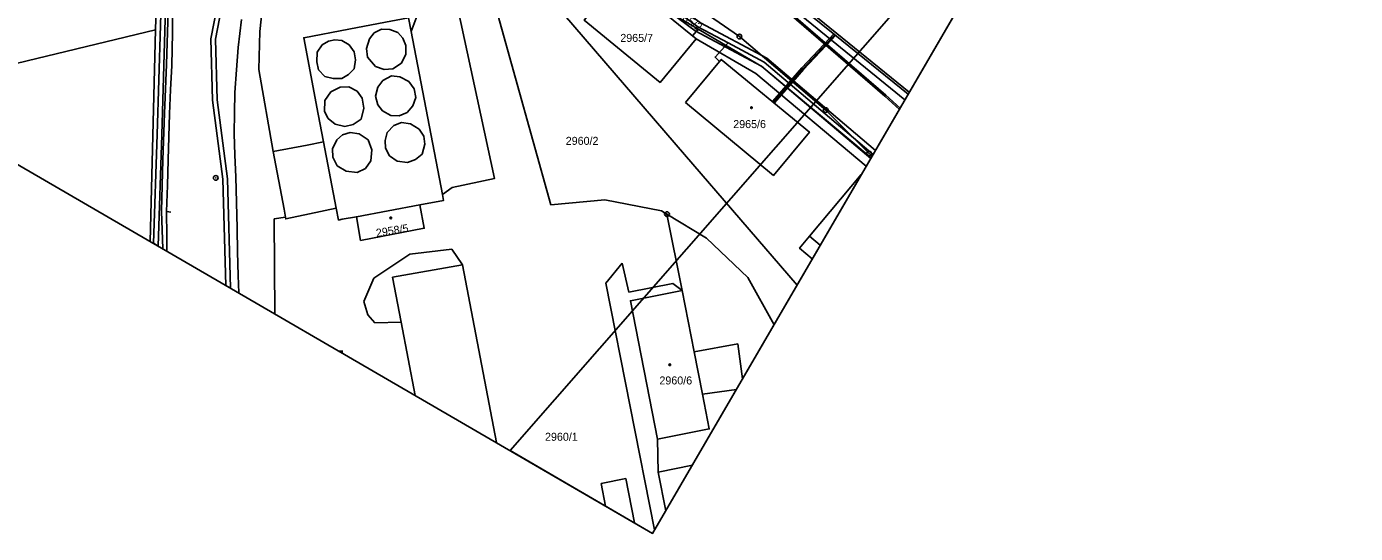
# Model space of a CAD drawing. Extents: x -621168 to -620292, y -1122748 to -1122069.
# Drawn here: x -620574.7 to -620292.4, y -1122748.2 to -1122640.4 of the extents above; entities that cross this region are included whole.
import ezdxf

# ---------------------------------------------------------------- set-up
doc = ezdxf.new("R2010")
doc.units = 0
for name, color, linetype in [('CETIN', 7, 'Continuous'), ('GasNet', 7, 'Continuous'), ('Hranice parcel', 7, 'Continuous'), ('Parcelní čísla', 7, 'Continuous'), ('Rámečky', 7, 'Continuous'), ('Rámečky-tisk', 7, 'Continuous'), ('SSZT-DK', 7, 'Continuous'), ('VAS stoka', 7, 'Continuous'), ('VAS vodovod', 7, 'Continuous'), ('Vnitřní kresba', 7, 'Continuous'), ('Věcná břemena k části', 7, 'Continuous'), ('Značky bodu BP', 7, 'Continuous'), ('Značky budov', 7, 'Continuous'), ('ČD-T', 7, 'Continuous')]:
    doc.layers.add(name, color=color, linetype=linetype)

msp = doc.modelspace()

# ---------------------------------------------------------------- linework, layer by layer
at = {"layer": 'CETIN'}
for points in [[(-620466.49, -1122590.92), (-620402.98, -1122642.16)], [(-620402.98, -1122642.16), (-620404.74, -1122644.03), (-620409.77, -1122649.38), (-620413.72, -1122653.89), (-620414.65, -1122654.95), (-620416.03, -1122656.53)], [(-620404.74, -1122644.03), (-620409.77, -1122649.38)], [(-620402.98, -1122642.16), (-620387.36, -1122654.76)]]:
    msp.add_lwpolyline(points, dxfattribs=at)
at = {"layer": 'GasNet'}
for points in [[(-620545.62, -1122586.36), (-620544.33, -1122585.86), (-620529.1, -1122581.91), (-620527.88, -1122581.68), (-620501.79, -1122593.01), (-620500.52, -1122592.53), (-620484.13, -1122585.56), (-620478.57, -1122583.14), (-620474.2, -1122586.82), (-620449.91, -1122606.86), (-620450.02, -1122607.5), (-620458.5, -1122620.02), (-620458.8, -1122620.62), (-620432.06, -1122640.49), (-620425.64, -1122643.91), (-620417.98, -1122647.99), (-620394.83, -1122667.62)], [(-620543.45, -1122595.16), (-620543.47, -1122603.15), (-620543.79, -1122613), (-620544.07, -1122623.3), (-620544.52, -1122634.84), (-620544.92, -1122648.49), (-620545.38, -1122658.87), (-620545.7, -1122668.76), (-620545.98, -1122679.66), (-620545.73, -1122687.65)], [(-620425.64, -1122643.91), (-620428.38, -1122646.91), (-620427.46, -1122647.86)]]:
    msp.add_lwpolyline(points, dxfattribs=at)
at = {"layer": 'Hranice parcel'}
for p, q in [((-620546.5, -1122612), (-620547.23, -1122641.1)), ((-620547.23, -1122641.1), (-620602.67, -1122654.54)), ((-620547.23, -1122641.1), (-620548.37, -1122686.11)), ((-620435.41, -1122696.52), (-620438.61, -1122680.28)), ((-620440.5, -1122735.14), (-620440.62, -1122728.09))]:
    msp.add_line(p, q, dxfattribs=at)
for points in [[(-620485.21, -1122574.33), (-620466.94, -1122589.51), (-620387.14, -1122654.39)], [(-620502.69, -1122605.61), (-620503.19, -1122607.95), (-620524.52, -1122636.25), (-620525.13, -1122641.47), (-620525.33, -1122649.53), (-620522.29, -1122666.99)], [(-620388.08, -1122656.01), (-620420.38, -1122629.64), (-620446.79, -1122609.88)], [(-620438.61, -1122680.28), (-620439.78, -1122679.56), (-620451.85, -1122677.25), (-620463.28, -1122678.3), (-620478.32, -1122624.38)], [(-620410.99, -1122695.4), (-620434.88, -1122667.63), (-620473.14, -1122623.15)], [(-620452.73, -1122622.13), (-620423.22, -1122642.55), (-620404.9, -1122658.18), (-620395.68, -1122667.41), (-620395.02, -1122667.94)], [(-620486.3, -1122676.15), (-620484.21, -1122674.6), (-620475.28, -1122672.75), (-620485.31, -1122626.04)], [(-620450.04, -1122631.61), (-620448.58, -1122629.86), (-620432.38, -1122643.03)], [(-620432.38, -1122643.03), (-620440.08, -1122652.3), (-620456.23, -1122639.05), (-620450.04, -1122631.61)], [(-620522.29, -1122666.99), (-620515.05, -1122665.61), (-620511.55, -1122664.94), (-620512.68, -1122659.03), (-620515.78, -1122642.8), (-620506.17, -1122640.97), (-620499.9, -1122639.77), (-620493.5, -1122638.55), (-620492.94, -1122641.47), (-620486.3, -1122676.15)], [(-620396.27, -1122670.08), (-620419.73, -1122650.41), (-620432.38, -1122643.03)], [(-620434.7, -1122656.53), (-620427.07, -1122647.39), (-620408.37, -1122662.86), (-620416.01, -1122672.06), (-620434.7, -1122656.53)], [(-620522.29, -1122666.99), (-620519.96, -1122679.22), (-620519.64, -1122680.92)], [(-620407.74, -1122689.82), (-620410.45, -1122687.55), (-620408.32, -1122685), (-620397.34, -1122671.88), (-620397.32, -1122671.9)], [(-620519.64, -1122680.92), (-620519.58, -1122681.29), (-620514.56, -1122680.24), (-620508.86, -1122679.05), (-620508.38, -1122681.54), (-620507.59, -1122681.39), (-620504.59, -1122680.83), (-620503.71, -1122685.86), (-620490.19, -1122683.29), (-620491.13, -1122678.32), (-620486.07, -1122677.38), (-620486.3, -1122676.15)], [(-620438.61, -1122680.28), (-620430.21, -1122685.42), (-620421.46, -1122693.76), (-620415.87, -1122703.8)], [(-620519.64, -1122680.92), (-620522.03, -1122681.32), (-620521.9, -1122701.5)], [(-620492.12, -1122718.82), (-620495.08, -1122703.28), (-620496.9, -1122693.7), (-620482.03, -1122691.1)], [(-620482.03, -1122691.1), (-620474.85, -1122728.86)], [(-620440.62, -1122728.09), (-620446.38, -1122698.69), (-620435.41, -1122696.52)], [(-620440.62, -1122728.09), (-620429.62, -1122725.94), (-620431.07, -1122718.59), (-620432.85, -1122709.54), (-620435.41, -1122696.52)], [(-620508.34, -1122709.39), (-620507.61, -1122709.36), (-620507.58, -1122709.83)], [(-620433.21, -1122733.63), (-620440.5, -1122735.14)], [(-620438.86, -1122743.34), (-620440.5, -1122735.14)]]:
    msp.add_lwpolyline(points, dxfattribs=at)
at = {"layer": 'Rámečky'}
msp.add_line((-620351.12, -1122592.44), (-620471.94, -1122730.56), dxfattribs=at)
msp.add_lwpolyline([(-620471.94, -1122730.56), (-620441.66, -1122748.16), (-620351.12, -1122592.44)], dxfattribs=at)
at = {"layer": 'Rámečky-tisk'}
msp.add_line((-620351.12, -1122592.44), (-620471.94, -1122730.56), dxfattribs=at)
for points in [[(-621018.54, -1122069.17), (-621167.83, -1122325.92), (-620441.66, -1122748.16)], [(-620441.66, -1122748.16), (-620292.37, -1122491.41), (-621018.54, -1122069.17)], [(-620471.94, -1122730.56), (-620441.66, -1122748.16), (-620351.12, -1122592.44)]]:
    msp.add_lwpolyline(points, dxfattribs=at)
at = {"layer": 'SSZT-DK'}
msp.add_lwpolyline([(-621084.33, -1122182.33), (-621080.25, -1122184.04), (-621051.5, -1122198.93), (-620999.37, -1122227), (-620959.93, -1122250.54), (-620931.35, -1122267.52), (-620900.27, -1122286.47), (-620889.15, -1122293.45), (-620783.74, -1122358.82), (-620712.75, -1122398.18), (-620653.12, -1122435.23), (-620617.36, -1122456.74), (-620574.42, -1122482.6), (-620528.16, -1122511.11), (-620496.31, -1122530.83), (-620515.02, -1122558.81), (-620500.38, -1122568.61), (-620465.39, -1122591.45), (-620452.16, -1122605.02), (-620438.23, -1122615.5), (-620392.31, -1122655.21), (-620389.25, -1122658.02)], dxfattribs=at)
at = {"layer": 'VAS stoka'}
msp.add_lwpolyline([(-620529.59, -1122697.03), (-620529.71, -1122693.36), (-620529.82, -1122688.3), (-620529.93, -1122683.25), (-620530.07, -1122677.82), (-620530.21, -1122672.39), (-620530.38, -1122667.76), (-620530.55, -1122663.12), (-620530.49, -1122658.76), (-620530.43, -1122654.4), (-620530.06, -1122649.64), (-620529.7, -1122644.88), (-620528.99, -1122638.95)], dxfattribs=at)
at = {"layer": 'VAS vodovod'}
msp.add_line((-620433.19, -1122642.42), (-620431.98, -1122640.97), dxfattribs=at)
for points in [[(-620395.25, -1122668.33), (-620418.43, -1122648.88), (-620439.22, -1122636.74), (-620439.29, -1122636.69), (-620439.37, -1122636.64), (-620460.45, -1122621.06), (-620460.7, -1122620.9), (-620459.95, -1122619.77), (-620451.51, -1122607.79), (-620450.89, -1122606.96), (-620476.53, -1122586.08), (-620476.53, -1122586.08), (-620476.87, -1122585.61)], [(-620543.55, -1122634.84), (-620543.68, -1122641.77), (-620543.81, -1122648.71), (-620544.05, -1122653.84), (-620544.28, -1122658.97), (-620544.43, -1122663.85), (-620544.59, -1122668.72), (-620544.75, -1122674.23), (-620544.92, -1122679.73), (-620544.87, -1122684.99), (-620544.84, -1122688.17)], [(-620544.92, -1122679.73), (-620544.45, -1122679.79), (-620543.99, -1122679.84)]]:
    msp.add_lwpolyline(points, dxfattribs=at)
at = {"layer": 'Vnitřní kresba'}
for p, q in [((-620487.46, -1122626.56), (-620492.94, -1122641.47)), ((-620500.81, -1122641.76), (-620499.26, -1122640.98)), ((-620499.26, -1122640.98), (-620497.47, -1122641.06)), ((-620497.47, -1122641.06), (-620495.76, -1122641.68)), ((-620511.84, -1122644.32), (-620510.52, -1122643.55)), ((-620510.52, -1122643.55), (-620509.2, -1122643.23)), ((-620509.2, -1122643.23), (-620507.65, -1122643.39)), ((-620507.65, -1122643.39), (-620506.09, -1122644.32)), ((-620502.44, -1122645.1), (-620501.82, -1122643)), ((-620501.82, -1122643), (-620500.81, -1122641.76)), ((-620495.76, -1122641.68), (-620494.75, -1122642.92)), ((-620494.75, -1122642.92), (-620494.06, -1122644.48)), ((-620513, -1122647.9), (-620512.93, -1122645.88)), ((-620512.93, -1122645.88), (-620511.84, -1122644.32)), ((-620506.09, -1122644.32), (-620505.08, -1122645.8)), ((-620505.08, -1122645.8), (-620504.77, -1122647.51)), ((-620502.21, -1122646.96), (-620502.44, -1122645.1)), ((-620500.5, -1122648.9), (-620502.21, -1122646.96)), ((-620494.06, -1122646.26), (-620494.99, -1122648.21)), ((-620494.06, -1122644.48), (-620494.06, -1122646.26)), ((-620512.62, -1122649.6), (-620513, -1122647.9)), ((-620511.3, -1122651), (-620512.62, -1122649.6)), ((-620505.08, -1122649.37), (-620506.25, -1122650.61)), ((-620504.77, -1122647.51), (-620505.08, -1122649.37)), ((-620498.71, -1122649.52), (-620500.5, -1122648.9)), ((-620496.85, -1122649.37), (-620498.71, -1122649.52)), ((-620494.99, -1122648.21), (-620496.85, -1122649.37)), ((-620509.51, -1122651.47), (-620511.3, -1122651)), ((-620507.65, -1122651.47), (-620509.51, -1122651.47)), ((-620506.25, -1122650.61), (-620507.65, -1122651.47)), ((-620500.03, -1122653.33), (-620498.95, -1122651.85)), ((-620498.95, -1122651.85), (-620497.16, -1122650.92)), ((-620497.16, -1122650.92), (-620495.38, -1122651.08)), ((-620495.38, -1122651.08), (-620493.43, -1122652.09)), ((-620493.43, -1122652.09), (-620492.35, -1122653.64)), ((-620511.3, -1122656.13), (-620510.05, -1122654.26)), ((-620510.05, -1122654.26), (-620508.03, -1122653.33)), ((-620508.03, -1122653.33), (-620506.17, -1122653.25)), ((-620506.17, -1122653.25), (-620504.46, -1122654.18)), ((-620504.46, -1122654.18), (-620503.37, -1122655.66)), ((-620500.5, -1122655.19), (-620500.03, -1122653.33)), ((-620500.03, -1122657.06), (-620500.5, -1122655.19)), ((-620492.35, -1122653.64), (-620491.96, -1122655.5)), ((-620511.37, -1122658.46), (-620511.3, -1122656.13)), ((-620502.99, -1122657.76), (-620503.61, -1122660.09)), ((-620503.37, -1122655.66), (-620502.99, -1122657.76)), ((-620499.03, -1122658.3), (-620500.03, -1122657.06)), ((-620492.58, -1122657.29), (-620493.82, -1122658.69)), ((-620491.96, -1122655.5), (-620492.58, -1122657.29)), ((-620510.6, -1122659.93), (-620511.37, -1122658.46)), ((-620509.12, -1122661.17), (-620510.6, -1122659.93)), ((-620503.61, -1122660.09), (-620505.24, -1122661.25)), ((-620497.24, -1122659.31), (-620499.03, -1122658.3)), ((-620495.53, -1122659.39), (-620497.24, -1122659.31)), ((-620496.62, -1122661.48), (-620494.99, -1122660.79)), ((-620493.82, -1122658.69), (-620495.53, -1122659.39)), ((-620494.99, -1122660.79), (-620493.12, -1122661.1)), ((-620507.02, -1122661.64), (-620509.12, -1122661.17)), ((-620508.73, -1122664.51), (-620507.57, -1122663.43)), ((-620507.57, -1122663.43), (-620505.94, -1122662.96)), ((-620505.24, -1122661.25), (-620507.02, -1122661.64)), ((-620505.94, -1122662.96), (-620504, -1122663.19)), ((-620504, -1122663.19), (-620502.06, -1122664.51)), ((-620498.48, -1122664.67), (-620498.02, -1122662.96)), ((-620498.02, -1122662.96), (-620496.62, -1122661.48)), ((-620493.12, -1122661.1), (-620491.26, -1122662.26)), ((-620491.26, -1122662.26), (-620490.25, -1122663.74)), ((-620490.25, -1122663.74), (-620490.02, -1122665.44)), ((-620508.86, -1122679.05), (-620511.55, -1122664.94)), ((-620509.67, -1122666.38), (-620508.73, -1122664.51)), ((-620509.59, -1122668.16), (-620509.67, -1122666.38)), ((-620502.06, -1122664.51), (-620501.28, -1122666.61)), ((-620501.28, -1122666.61), (-620501.51, -1122668.94)), ((-620498.41, -1122666.3), (-620498.48, -1122664.67)), ((-620497.55, -1122667.93), (-620498.41, -1122666.3)), ((-620490.02, -1122665.44), (-620490.64, -1122667.54)), ((-620508.66, -1122670.03), (-620509.59, -1122668.16)), ((-620501.51, -1122668.94), (-620502.68, -1122670.57)), ((-620495.92, -1122669.02), (-620497.55, -1122667.93)), ((-620493.75, -1122669.33), (-620495.92, -1122669.02)), ((-620492.04, -1122668.71), (-620493.75, -1122669.33)), ((-620490.64, -1122667.54), (-620492.04, -1122668.71)), ((-620506.79, -1122671.19), (-620508.66, -1122670.03)), ((-620504.46, -1122671.42), (-620506.79, -1122671.19)), ((-620502.68, -1122670.57), (-620504.46, -1122671.42)), ((-620504.59, -1122680.83), (-620491.13, -1122678.32)), ((-620406.05, -1122686.9), (-620408.32, -1122685)), ((-620500.9, -1122693.92), (-620493.22, -1122688.81)), ((-620493.22, -1122688.81), (-620484.3, -1122687.75)), ((-620484.3, -1122687.75), (-620482.03, -1122691.1)), ((-620448.12, -1122690.72), (-620451.61, -1122694.97)), ((-620446.75, -1122696.88), (-620448.12, -1122690.72)), ((-620503.01, -1122698.89), (-620500.9, -1122693.92)), ((-620451.61, -1122694.97), (-620441.23, -1122747.41)), ((-620437.36, -1122695.04), (-620446.75, -1122696.88)), ((-620437.36, -1122695.04), (-620435.41, -1122696.52)), ((-620502.18, -1122701.71), (-620503.01, -1122698.89)), ((-620500.67, -1122703.36), (-620502.18, -1122701.71)), ((-620495.08, -1122703.28), (-620500.67, -1122703.36)), ((-620432.85, -1122709.54), (-620423.56, -1122707.88)), ((-620423.56, -1122707.88), (-620422.57, -1122715.32)), ((-620423.88, -1122717.57), (-620431.07, -1122718.59)), ((-620447.35, -1122736.5), (-620452.59, -1122737.55)), ((-620445.54, -1122745.91), (-620447.35, -1122736.5)), ((-620451.65, -1122742.35), (-620452.59, -1122737.55))]:
    msp.add_line(p, q, dxfattribs=at)
at = {"layer": 'Věcná břemena k části'}
for p, q in [((-620395.34, -1122668.49), (-620394.32, -1122666.74)), ((-620547.72, -1122686.49), (-620546.73, -1122687.07)), ((-620532.32, -1122695.44), (-620531.3, -1122696.04))]:
    msp.add_line(p, q, dxfattribs=at)
for points in [[(-620394.32, -1122666.74), (-620417.42, -1122647.16), (-620431.52, -1122639.64), (-620457.44, -1122620.38), (-620448.45, -1122606.75), (-620478.4, -1122581.98), (-620488.36, -1122586.21), (-620487.32, -1122587.95), (-620478.74, -1122584.3), (-620451.11, -1122607.15), (-620460.16, -1122620.86), (-620432.6, -1122641.34), (-620418.54, -1122648.82), (-620395.34, -1122668.49)], [(-620545.88, -1122628.46), (-620546.91, -1122663.38), (-620547.72, -1122686.49)], [(-620546.73, -1122687.07), (-620545.91, -1122663.42), (-620544.9, -1122629)], [(-620534.2, -1122636.18), (-620535.53, -1122643.03), (-620535.16, -1122656.08), (-620532.94, -1122672.87), (-620532.32, -1122695.44)], [(-620531.3, -1122696.04), (-620531.94, -1122672.79), (-620534.16, -1122656), (-620534.53, -1122643.11), (-620533.24, -1122636.48)]]:
    msp.add_lwpolyline(points, dxfattribs=at)
for points in [[(-620414.7, -1122654.63), (-620414.31, -1122654.95), (-620411.9, -1122652.2), (-620409.58, -1122649.55), (-620403.69, -1122643.27), (-620402.81, -1122642.33), (-620403.17, -1122641.99), (-620404.07, -1122642.95), (-620409.97, -1122649.21), (-620412.29, -1122651.87)], [(-620415.83, -1122656.69), (-620414.31, -1122654.95), (-620414.7, -1122654.63), (-620416.22, -1122656.37)]]:
    msp.add_lwpolyline(points, close=True, dxfattribs=at)
at = {"layer": 'Značky bodu BP'}
for centre, radius in [((-620423.22, -1122642.55), 0.5), ((-620423.22, -1122642.55), 0.0303), ((-620404.9, -1122658.18), 0.5), ((-620404.9, -1122658.18), 0.0303), ((-620395.68, -1122667.41), 0.5), ((-620395.68, -1122667.41), 0.0303), ((-620534.45, -1122672.58), 0.5), ((-620534.45, -1122672.58), 0.0303), ((-620438.61, -1122680.28), 0.5), ((-620438.61, -1122680.28), 0.0303)]:
    msp.add_circle(centre, radius, dxfattribs=at)
at = {"layer": 'Značky budov'}
for centre in [(-620420.66, -1122657.67), (-620497.29, -1122681.09), (-620438.02, -1122712.31)]:
    msp.add_circle(centre, 0.175, dxfattribs=at)
at = {"layer": 'ČD-T'}
msp.add_lwpolyline([(-621084.19, -1122182.07), (-621080.06, -1122183.8), (-621051.32, -1122198.69), (-620999.18, -1122226.77), (-620959.75, -1122250.31), (-620931.16, -1122267.28), (-620900.08, -1122286.23), (-620888.96, -1122293.22), (-620783.56, -1122358.58), (-620712.56, -1122397.94), (-620652.93, -1122435), (-620617.18, -1122456.5), (-620574.24, -1122482.37), (-620527.97, -1122510.87), (-620481.08, -1122540.08), (-620497, -1122565.38), (-620499.27, -1122568.98), (-620465.21, -1122591.22), (-620451.97, -1122604.79), (-620438.05, -1122615.26), (-620392.12, -1122654.98), (-620389.1, -1122657.76)], dxfattribs=at)

# ---------------------------------------------------------------- texts
at = {"layer": 'Parcelní čísla'}
for s, rotation, p in [('2965/2', 325, (-620437.6, -1122637.48)), ('2958/5', 9, (-620500.28, -1122685.15))]:
    msp.add_text(s, height=1.7, rotation=rotation, dxfattribs=at).set_placement(p)
for s, p in [('2965/7', (-620448.53, -1122643.68)), ('2965/6', (-620424.54, -1122662)), ('2960/2', (-620460.12, -1122665.56)), ('2960/6', (-620440.22, -1122716.49)), ('2960/1', (-620464.52, -1122728.46))]:
    msp.add_text(s, height=1.7, dxfattribs=at).set_placement(p)

doc.saveas('drawing.dxf')
